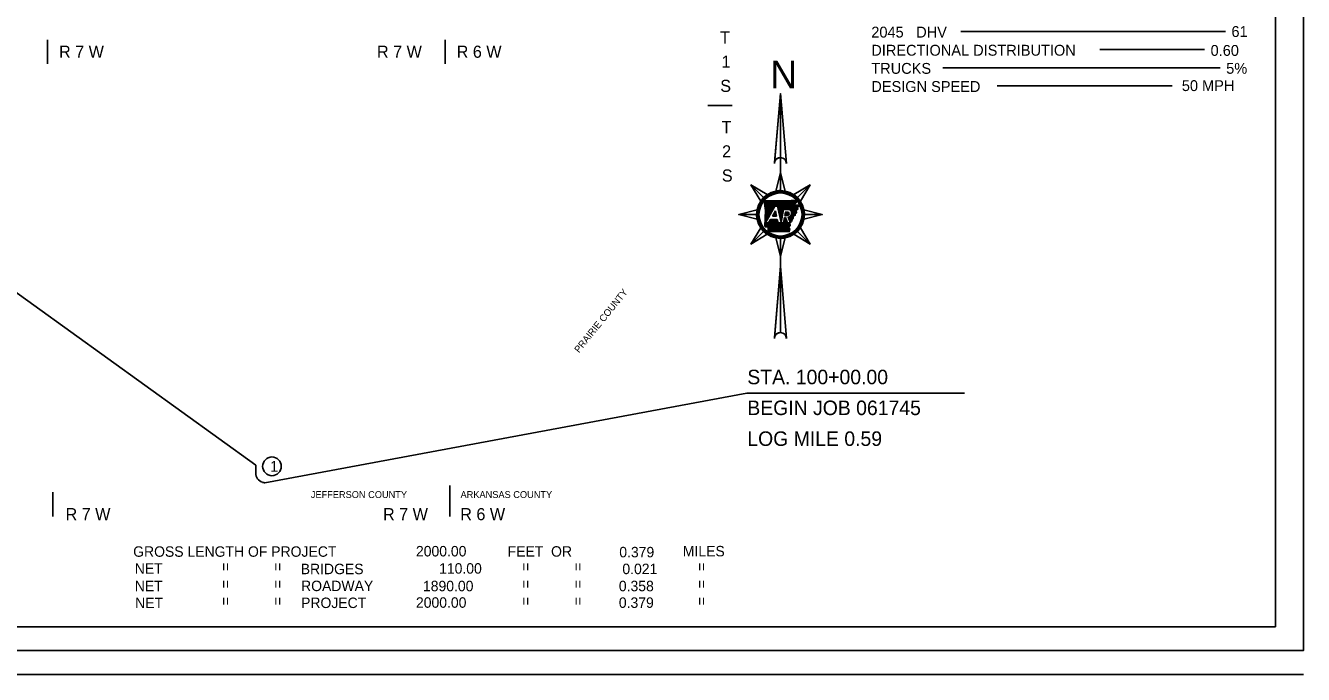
# Model space of a CAD drawing. Extents: x 76 to 6945, y -3933 to 2152.
# Drawn here: x 1245 to 3359, y -21 to 1052 of the extents above; entities that cross this region are included whole.
import ezdxf

# ---------------------------------------------------------------- set-up
doc = ezdxf.new("R2010")
doc.units = 0
doc.layers.add('R_Draft', color=7, linetype='Continuous')
doc.layers.add('R_No Plot', color=7, linetype='Continuous')

msp = doc.modelspace()

# ---------------------------------------------------------------- linework, layer by layer
at = {"layer": 'R_Draft'}
for p, q in [((3313.4, 57.7), (3313.4, 2112.1)), ((2792.4, 1042.4), (3230.6, 1042.4)), ((1281.1, 988.8), (1281.1, 1028.8)), ((1939.3, 988.8), (1939.3, 1028.8)), ((3022.4, 1012.4), (3195.8, 1012.4)), ((2762.4, 982.4), (3221.4, 982.4)), ((2852.4, 952.4), (3142.4, 952.4)), ((2494, 939.6), (2484.3, 825.6)), ((2494, 939.6), (2494, 783.5)), ((2494, 833.9), (2494, 939.6)), ((2413.9, 920), (2373.9, 920)), ((2484.4, 827.2), (2484.8, 827.7)), ((2484.5, 827.8), (2485.4, 828.7)), ((2494, 808.9), (2486.3, 778.5)), ((2494, 779.2), (2494, 808.9)), ((2445.1, 788.6), (2466.1, 767.7)), ((2466.1, 767.7), (2445.1, 788.6)), ((2445.1, 788.6), (2461.2, 761.7)), ((2542.9, 788.6), (2516, 772.6)), ((2522, 767.7), (2542.9, 788.6)), ((2522, 767.7), (2542.9, 788.6)), ((2467.1, 762), (2467.4, 762.3)), ((2467.2, 761), (2468.5, 762.3)), ((2467.3, 760), (2469.6, 762.3)), ((2467.4, 759), (2470.8, 762.3)), ((2467.6, 758), (2471.9, 762.3)), ((2467.7, 757), (2473, 762.3)), ((2467.8, 756), (2474.1, 762.3)), ((2467.9, 755), (2475.2, 762.3)), ((2468.1, 754), (2476.4, 762.3)), ((2468.2, 753), (2477.5, 762.3)), ((2468.3, 752), (2478.6, 762.3)), ((2468.4, 751.1), (2479.7, 762.3)), ((2468.6, 750.1), (2480.8, 762.3)), ((2468.7, 737.9), (2493.1, 762.3)), ((2468.7, 749.1), (2481.9, 762.3)), ((2468.8, 739.1), (2492, 762.3)), ((2468.8, 740.2), (2490.9, 762.3)), ((2468.8, 741.4), (2489.8, 762.3)), ((2468.8, 748.1), (2483.1, 762.3)), ((2468.9, 742.5), (2488.7, 762.3)), ((2468.9, 743.7), (2487.5, 762.3)), ((2468.9, 744.9), (2486.4, 762.3)), ((2468.9, 747.1), (2484.2, 762.3)), ((2469, 746), (2485.3, 762.3)), ((2485.3, 753.4), (2494.3, 762.4)), ((2486.4, 753.4), (2495.4, 762.4)), ((2487.5, 753.4), (2496.5, 762.4)), ((2488.7, 753.4), (2497.6, 762.4)), ((2489.4, 753), (2498.8, 762.4)), ((2489.6, 752.1), (2499.9, 762.4)), ((2489.8, 751.1), (2501, 762.4)), ((2490, 750.2), (2502.2, 762.5)), ((2490.2, 749.3), (2503.3, 762.5)), ((2490.3, 748.4), (2504.5, 762.5)), ((2490.5, 747.5), (2505.6, 762.5)), ((2490.7, 746.5), (2506.7, 762.5)), ((2490.9, 745.6), (2507.9, 762.5)), ((2491.1, 744.7), (2509, 762.6)), ((2491.3, 743.8), (2510.1, 762.6)), ((2491.5, 742.9), (2511.3, 762.6)), ((2491.7, 741.9), (2512.4, 762.6)), ((2491.9, 741), (2513.6, 762.6)), ((2499.7, 747.7), (2514.7, 762.7)), ((2500.8, 747.7), (2515.8, 762.7)), ((2501.9, 747.7), (2517, 762.7)), ((2503, 747.7), (2518.1, 762.7)), ((2504.2, 747.7), (2519.3, 762.8)), ((2505.3, 747.7), (2519.5, 761.9)), ((2468.5, 732.1), (2477.9, 741.5)), ((2468.6, 735.6), (2482.3, 749.3)), ((2468.6, 734.5), (2480.8, 746.7)), ((2468.6, 733.3), (2479.4, 744.1)), ((2468.7, 736.8), (2483.8, 751.9)), ((2469, 725.9), (2484.6, 753.4)), ((2480.5, 736.7), (2485.6, 745.7)), ((2480.6, 736.7), (2486.3, 742.4)), ((2481.7, 736.7), (2486.5, 741.5)), ((2481.9, 739.1), (2486.1, 743.3)), ((2482.8, 736.7), (2486.7, 740.6)), ((2483.4, 741.7), (2485.9, 744.3)), ((2484.6, 753.4), (2489.3, 753.4)), ((2484.8, 744.3), (2485.7, 745.2)), ((2492.1, 740.1), (2498.5, 746.4)), ((2492.3, 739.2), (2498.2, 745.1)), ((2492.5, 738.3), (2498, 743.7)), ((2492.7, 737.3), (2497.8, 742.4)), ((2492.9, 736.4), (2497.5, 741)), ((2498.7, 747.7), (2509.5, 747.7)), ((2501, 737.9), (2506.9, 743.8)), ((2501.3, 739.2), (2505.8, 743.8)), ((2501.5, 740.6), (2504.7, 743.8)), ((2501.7, 741.9), (2503.6, 743.8)), ((2502, 743.3), (2502.4, 743.8)), ((2502.1, 743.8), (2507.1, 743.8)), ((2502.2, 737.9), (2507.5, 743.3)), ((2503.3, 737.9), (2507.9, 742.5)), ((2504.4, 737.9), (2508.1, 741.6)), ((2505.5, 737.9), (2508, 740.4)), ((2506.4, 747.7), (2520.1, 761.3)), ((2507.5, 747.7), (2520.2, 760.4)), ((2507.6, 733.2), (2520, 745.6)), ((2507.9, 732.4), (2520.2, 744.7)), ((2508.2, 731.6), (2520.4, 743.8)), ((2508.5, 730.8), (2520.6, 742.9)), ((2508.6, 747.7), (2517.7, 756.7)), ((2509.6, 747.6), (2517.4, 755.3)), ((2510.3, 747.1), (2518.6, 755.4)), ((2510.8, 746.5), (2519.8, 755.5)), ((2511.3, 745.8), (2521, 755.5)), ((2511.3, 738), (2519.8, 746.5)), ((2511.7, 745.1), (2522.1, 755.6)), ((2512, 744.4), (2523.3, 755.6)), ((2512.2, 740.1), (2522.4, 750.2)), ((2512.3, 743.5), (2524.4, 755.6)), ((2512.5, 742.5), (2524.9, 755)), ((2512.5, 741.4), (2522.2, 751.2)), ((2521.1, 747.9), (2522.5, 749.2)), ((2524.4, 753.4), (2525.4, 754.4)), ((2563.2, 739.7), (2532.8, 747.4)), ((2424.8, 739.7), (2454.5, 739.7)), ((2454.5, 739.7), (2424.8, 739.7)), ((2424.8, 739.7), (2455.2, 732)), ((2468.2, 720.6), (2473.4, 725.9)), ((2468.2, 721.7), (2472.3, 725.9)), ((2468.2, 722.9), (2471.2, 725.9)), ((2468.3, 726.4), (2470.6, 728.7)), ((2468.3, 725.2), (2469.2, 726.1)), ((2468.3, 724), (2470.1, 725.9)), ((2468.4, 729.8), (2475, 736.4)), ((2468.4, 728.7), (2473.5, 733.8)), ((2468.4, 727.5), (2472.1, 731.2)), ((2468.5, 731), (2476.5, 739)), ((2468.6, 719.9), (2480.3, 731.6)), ((2474.4, 725.9), (2469, 725.9)), ((2469.2, 719.4), (2481.4, 731.6)), ((2470, 719.1), (2482.6, 731.6)), ((2471.4, 719.3), (2483.7, 731.6)), ((2472.5, 719.4), (2484.8, 731.6)), ((2473.4, 716.9), (2488.1, 731.6)), ((2473.4, 718), (2487, 731.6)), ((2473.4, 719.1), (2485.9, 731.6)), ((2473.4, 715.8), (2488.7, 731.1)), ((2473.4, 714.7), (2488.9, 730.2)), ((2473.4, 713.6), (2489.1, 729.3)), ((2473.4, 712.5), (2489.3, 728.4)), ((2473.4, 711.4), (2489.5, 727.4)), ((2477.7, 731.6), (2474.4, 725.9)), ((2474.6, 711.4), (2489.7, 726.5)), ((2475.7, 728.1), (2479.2, 731.6)), ((2475.7, 711.4), (2490.2, 725.9)), ((2476.8, 711.4), (2491.3, 725.9)), ((2477.1, 730.7), (2478.1, 731.6)), ((2488.6, 731.6), (2477.7, 731.6)), ((2477.9, 711.4), (2492.4, 725.9)), ((2479, 711.4), (2493.5, 725.9)), ((2480.1, 711.3), (2494.7, 725.9)), ((2480.5, 736.7), (2487.5, 736.7)), ((2481.3, 711.3), (2495.8, 725.9)), ((2482.4, 711.3), (2496.9, 725.9)), ((2483.5, 711.3), (2498, 725.9)), ((2483.9, 736.7), (2486.9, 739.7)), ((2484.6, 711.3), (2503.8, 730.6)), ((2485, 736.7), (2487.1, 738.7)), ((2485.7, 711.3), (2504.1, 729.8)), ((2486.2, 736.7), (2487.3, 737.8)), ((2486.8, 711.3), (2504.4, 728.9)), ((2487.3, 736.7), (2487.5, 736.9)), ((2488, 711.3), (2504.7, 728.1)), ((2489.1, 711.3), (2505, 727.3)), ((2498.9, 725.9), (2489.9, 725.9)), ((2490.2, 711.3), (2505.3, 726.5)), ((2491.3, 711.3), (2505.8, 725.9)), ((2492.4, 711.3), (2507, 725.9)), ((2493.1, 735.5), (2497.3, 739.7)), ((2493.3, 734.6), (2497, 738.3)), ((2493.5, 733.6), (2496.8, 737)), ((2493.5, 711.3), (2508.1, 725.9)), ((2493.7, 732.7), (2496.6, 735.6)), ((2493.9, 731.8), (2496.3, 734.3)), ((2494.1, 730.9), (2496.1, 732.9)), ((2494.3, 730), (2495.9, 731.5)), ((2494.5, 729), (2495.6, 730.2)), ((2494.7, 728.1), (2495.4, 728.8)), ((2494.7, 711.3), (2509.2, 725.9)), ((2494.9, 727.2), (2495.2, 727.5)), ((2495.8, 711.3), (2509.6, 725.1)), ((2496.9, 711.3), (2509.6, 724.1)), ((2498, 711.3), (2509.7, 723)), ((2499.1, 727), (2503.5, 731.4)), ((2499.1, 711.3), (2509.7, 721.9)), ((2499.4, 728.3), (2503.2, 732.2)), ((2499.6, 729.7), (2502.9, 733)), ((2499.8, 731), (2502.6, 733.8)), ((2500.1, 732.4), (2502.3, 734.6)), ((2500.3, 733.7), (2501.2, 734.6)), ((2502.3, 734.6), (2500.5, 734.6)), ((2501, 737.9), (2505.7, 737.9)), ((2505.6, 725.9), (2502.3, 734.6)), ((2510.3, 725.9), (2505.6, 725.9)), ((2506.9, 735.1), (2510.3, 725.9)), ((2507, 734.9), (2507.3, 735.2)), ((2507.3, 734), (2509.4, 736.2)), ((2508.8, 730), (2515.5, 736.7)), ((2509.1, 729.1), (2515.4, 735.4)), ((2509.4, 728.3), (2515.3, 734.2)), ((2509.7, 727.5), (2513.1, 730.9)), ((2510, 726.7), (2512.7, 729.3)), ((2516.8, 738), (2518.4, 739.5)), ((2533.5, 739.7), (2563.2, 739.7)), ((2533.5, 739.7), (2563.2, 739.7)), ((1085.2, 714.1), (1625.7, 325.1)), ((2445.1, 690.8), (2466.1, 711.8)), ((2466.1, 711.8), (2445.1, 690.8)), ((2445.1, 690.8), (2472, 706.9)), ((2494, 670.6), (2501.7, 700.9)), ((2494, 700.2), (2494, 700.2)), ((2494, 700.2), (2494, 573.7)), ((2494, 700.2), (2494, 670.6)), ((2500.2, 711.3), (2507.9, 719)), ((2501.3, 711.3), (2508.2, 718.2)), ((2502.5, 711.3), (2508.6, 717.4)), ((2503.6, 711.3), (2508.9, 716.6)), ((2504.7, 711.3), (2509.3, 715.9)), ((2505.8, 711.3), (2509.6, 715)), ((2506.9, 711.3), (2509, 713.4)), ((2508, 711.3), (2508.5, 711.8)), ((2522, 711.8), (2542.9, 690.8)), ((2522, 711.8), (2542.9, 690.8)), ((2542.9, 690.8), (2526.9, 717.7)), ((2494, 654), (2484.3, 536.1)), ((2494, 544.4), (2494, 654)), ((2438.3, 444.2), (1640.6, 295.8)), ((2438.3, 444.2), (2798.3, 444.2)), ((1625.5, 312.1), (1625.7, 323.3)), ((1625.7, 324.8), (1625.7, 325.1)), ((1625.7, 324.5), (1625.7, 324.8)), ((1625.7, 324.2), (1625.7, 324.5)), ((1625.7, 323.9), (1625.7, 324.2)), ((1625.7, 323.6), (1625.7, 323.9)), ((1625.7, 323.3), (1625.7, 323.6)), ((1637, 296.6), (1636.7, 296.7)), ((1637.3, 296.6), (1637, 296.6)), ((1637.6, 296.5), (1637.3, 296.6)), ((1637.9, 296.4), (1637.6, 296.5)), ((1638.1, 296.4), (1637.9, 296.4)), ((1638.4, 296.3), (1638.1, 296.4)), ((1638.7, 296.2), (1638.4, 296.3)), ((1639, 296.2), (1638.7, 296.2)), ((1639.3, 296.1), (1639, 296.2)), ((1639.6, 296), (1639.3, 296.1)), ((1290, 280.2), (1290, 240.2)), ((1639.9, 296), (1639.6, 296)), ((1640.2, 295.9), (1639.9, 296)), ((1640.5, 295.9), (1640.2, 295.9)), ((1640.6, 295.8), (1640.5, 295.9)), ((1946.9, 291.4), (1946.9, 240.2)), ((3313.4, 57.7), (151.6, 57.7)), ((85.9, 18.2), (3359.4, 18.2)), ((85.9, -21.1), (3359.4, -21.1))]:
    msp.add_line(p, q, dxfattribs=at)
for points in [[(2503.9, 824), (2494, 939.6), (2484.1, 824)], [(2486.3, 778.5), (2494, 808.9), (2501.7, 778.5)], [(2461.2, 761.7), (2445.1, 788.6), (2472, 772.6)], [(2516, 772.6), (2542.9, 788.6), (2526.9, 761.7)], [(2467, 762.3), (2482.4, 762.3), (2496, 762.4), (2511.9, 762.6), (2519.3, 762.8)], [(2468.1, 720.6), (2469, 746.5), (2467, 762.3)], [(2455.2, 732), (2424.8, 739.7), (2455.2, 747.4)], [(2485.6, 745.7), (2487.5, 736.7)], [(2489.3, 753.4), (2495, 726.6), (2498.7, 747.7)], [(2501, 737.9), (2502.1, 743.8)], [(2524.2, 755.7), (2525.5, 754.3), (2522.2, 751.6), (2522.6, 748.8), (2519.7, 746.9), (2520.7, 742.7), (2518.5, 740.7), (2518.3, 738.5), (2515.6, 737.5), (2515.2, 733.4), (2513.3, 731.3), (2512.3, 728.2), (2509.5, 725.7), (2509.8, 721.2), (2507.9, 719), (2509.6, 715.2), (2508.4, 711.3)], [(2517.1, 755.3), (2524.3, 755.7)], [(2532.8, 747.4), (2563.2, 739.7), (2532.8, 732)], [(2508.4, 711.3), (2473.4, 711.4), (2473.4, 719.1)], [(2489.9, 725.9), (2488.6, 731.6)], [(2500.5, 734.6), (2498.9, 725.9)], [(2472, 706.9), (2445.1, 690.8), (2461.2, 717.7)], [(2501.7, 700.9), (2494, 670.6), (2486.3, 700.9)], [(2526.9, 717.7), (2542.9, 690.8), (2516, 706.9)], [(2503.9, 534.5), (2494, 654), (2484.1, 534.5)]]:
    msp.add_lwpolyline(points, dxfattribs=at)
for centre, radius in [((2494, 739.7), 39.5), ((2494, 739.7), 37.5), ((2494, 739.7), 35.6), ((1652.4, 323.1), 15.5)]:
    msp.add_circle(centre, radius, dxfattribs=at)
for centre, radius, start, end in [((2494, 824), 9.88, 0, 180), ((2494, 824), 9.88, 90, 170.2296), ((2494, 739.7), 39.5, 135, 146.2291), ((2494, 739.7), 39.5, 90, 101.2291), ((2494, 739.7), 39.5, 45, 56.2291), ((2504.6, 741.3), 3.58, 288.1268, 43.8902), ((2505.5, 741.9), 7, 281.8626, 54.8705), ((2494, 739.7), 39.5, 0, 11.2291), ((2494, 739.7), 39.5, 180, 191.2291), ((2494, 739.7), 39.5, 225, 236.2291), ((2494, 739.7), 39.5, 270, 281.2291), ((2494, 739.7), 39.5, 315, 326.2291), ((2494, 534.5), 9.88, 0, 180), ((2494, 534.5), 9.88, 90, 170.5511), ((1641.3, 311.9), 15.8, 178.9649, 253.1852)]:
    msp.add_arc(centre, radius, start, end, dxfattribs=at)
for points in [[(2519.3, 762.8), (2519.4, 762.4), (2519.5, 762.1), (2519.5, 761.7), (2519.7, 761.6), (2520, 761.4), (2520.2, 761.1), (2520.3, 760.8), (2520.2, 760.5), (2520.2, 760.1), (2520.2, 759.8), (2520.1, 759.5), (2519.9, 759.2), (2519.6, 759.1), (2519.4, 758.9), (2519.3, 758.6), (2519.1, 758.4), (2518.8, 758.2), (2518.6, 758), (2518.4, 757.7), (2518.3, 757.4), (2518.1, 757.2), (2517.9, 757), (2517.7, 756.7), (2517.6, 756.5), (2517.4, 756.2), (2517.3, 755.9), (2517.2, 755.7), (2517.2, 755.6)], [(2473.4, 719.1), (2473.5, 719.1), (2473.3, 719.2), (2473, 719.3), (2472.7, 719.3), (2472.4, 719.4), (2472.1, 719.4), (2471.8, 719.6), (2471.5, 719.4), (2471.1, 719.2), (2470.9, 719.4), (2470.6, 719.3), (2470.4, 719.4), (2470.1, 719.1), (2469.8, 719.2), (2469.6, 719.1), (2469.3, 719.2), (2469.2, 719.5), (2468.9, 719.5), (2468.7, 719.7), (2468.5, 720), (2468.4, 720.2), (2468.1, 720.6)]]:
    msp.add_spline(points, degree=3, dxfattribs=at)
at = {"layer": 'R_No Plot'}
msp.add_lwpolyline([(76.1, 2151.6), (3359.4, 2151.6), (3359.4, 18.2), (76.1, 18.2)], close=True, dxfattribs=at)

# ---------------------------------------------------------------- texts
at = {"layer": 'R_Draft'}
for s, height, p in [('T', 20, (2393.9, 1022.5)), ('2045', 18, (2644.3, 1032.4)), (' DHV', 18, (2711.9, 1032.4)), ('61', 18, (3240.3, 1033.4)), ('R 7 W', 20, (1300, 999)), ('R 7 W', 20, (1826.2, 999)), ('R 6 W', 20, (1958.1, 999)), ('DIRECTIONAL DISTRIBUTION', 18, (2644.3, 1002.4)), ('0.60', 18, (3205.8, 1002.1)), ('1', 20, (2396.4, 982.5)), ('N', 45.6, (2477.3, 948.5)), ('TRUCKS', 18, (2644.3, 972.4)), ('5%', 18, (3231.6, 972.5)), ('S', 20, (2394.3, 942.5)), ('DESIGN SPEED', 18, (2644.3, 942.4)), ('50 MPH', 18, (3158.2, 943.9)), ('T', 20, (2396.5, 874.2)), ('2', 20, (2397.3, 834.2)), ('S', 20, (2396.9, 794.2)), ('DWB 7-27-17', 0.768, (2491.6, 703.5)), ('STA. 100+00.00', 24, (2439.1, 458.9)), ('BEGIN JOB 061745', 24, (2439.1, 407.9)), ('LOG MILE 0.59 ', 24, (2439.1, 356.9)), ('1', 18, (1649.4, 314.1)), ('JEFFERSON COUNTY', 11.4, (1716.7, 270.7)), ('ARKANSAS COUNTY', 11.4, (1964.5, 270.7)), ('R 7 W', 20, (1310.8, 234)), ('R 7 W', 20, (1836.2, 234)), ('R 6 W', 20, (1964, 234)), ('GROSS LENGTH OF PROJECT', 17.28, (1422.7, 173.5)), ('2000.00', 17.28, (1890.7, 174.1)), ('FEET  OR', 17.28, (2042.4, 173.7)), ('MILES', 17.28, (2332.4, 174.2)), ('0.379', 17.28, (2227.2, 172.6)), ('NET', 17.28, (1425.3, 145.4)), ('BRIDGES', 17.28, (1700, 144.7)), ('110.00', 17.28, (1929, 145.6)), ('0.021', 17.28, (2232.3, 144.8)), ('NET', 17.28, (1425.3, 116.6)), ('ROADWAY', 17.28, (1700.6, 116.7)), ('1890.00', 17.28, (1902.3, 116.5)), ('0.358', 17.28, (2226.5, 116.5)), ('NET', 17.28, (1426, 88.5)), ('PROJECT', 17.28, (1700.6, 88.7)), ('2000.00', 17.28, (1890.7, 89.2)), ('0.379', 17.28, (2226.5, 89))]:
    msp.add_text(s, height=height, dxfattribs=at).set_placement(p)
for s, height, rotation, p in [('PRAIRIE COUNTY', 11.4, 51.0156, (2160.5, 510)), ('=', 17.3, 90, (1583.9, 150.2)), ('=', 17.3, 90, (1670.3, 150.2)), ('=', 17.3, 90, (2080.7, 150.2)), ('=', 17.3, 90, (2167.1, 150.2)), ('=', 17.3, 90, (2371.6, 150.2)), ('=', 17.3, 90, (1583.9, 121.4)), ('=', 17.3, 90, (1670.3, 121.4)), ('=', 17.3, 90, (2080.7, 121.4)), ('=', 17.3, 90, (2167.1, 121.4)), ('=', 17.3, 90, (2371.6, 121.4)), ('=', 17.3, 90, (1583.9, 93.3)), ('=', 17.3, 90, (1670.3, 93.3)), ('=', 17.3, 90, (2080.7, 93.3)), ('=', 17.3, 90, (2167.1, 93.3)), ('=', 17.3, 90, (2371.6, 93.3))]:
    msp.add_text(s, height=height, rotation=rotation, dxfattribs=at).set_placement(p)

doc.saveas('drawing.dxf')
